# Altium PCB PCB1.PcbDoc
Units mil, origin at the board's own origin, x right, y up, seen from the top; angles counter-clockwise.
Board outline 6000 x 4000 mil, 2 copper layers (Top Layer, Bottom Layer); 44 components, 30 nets, 116 pads, 3 vias.
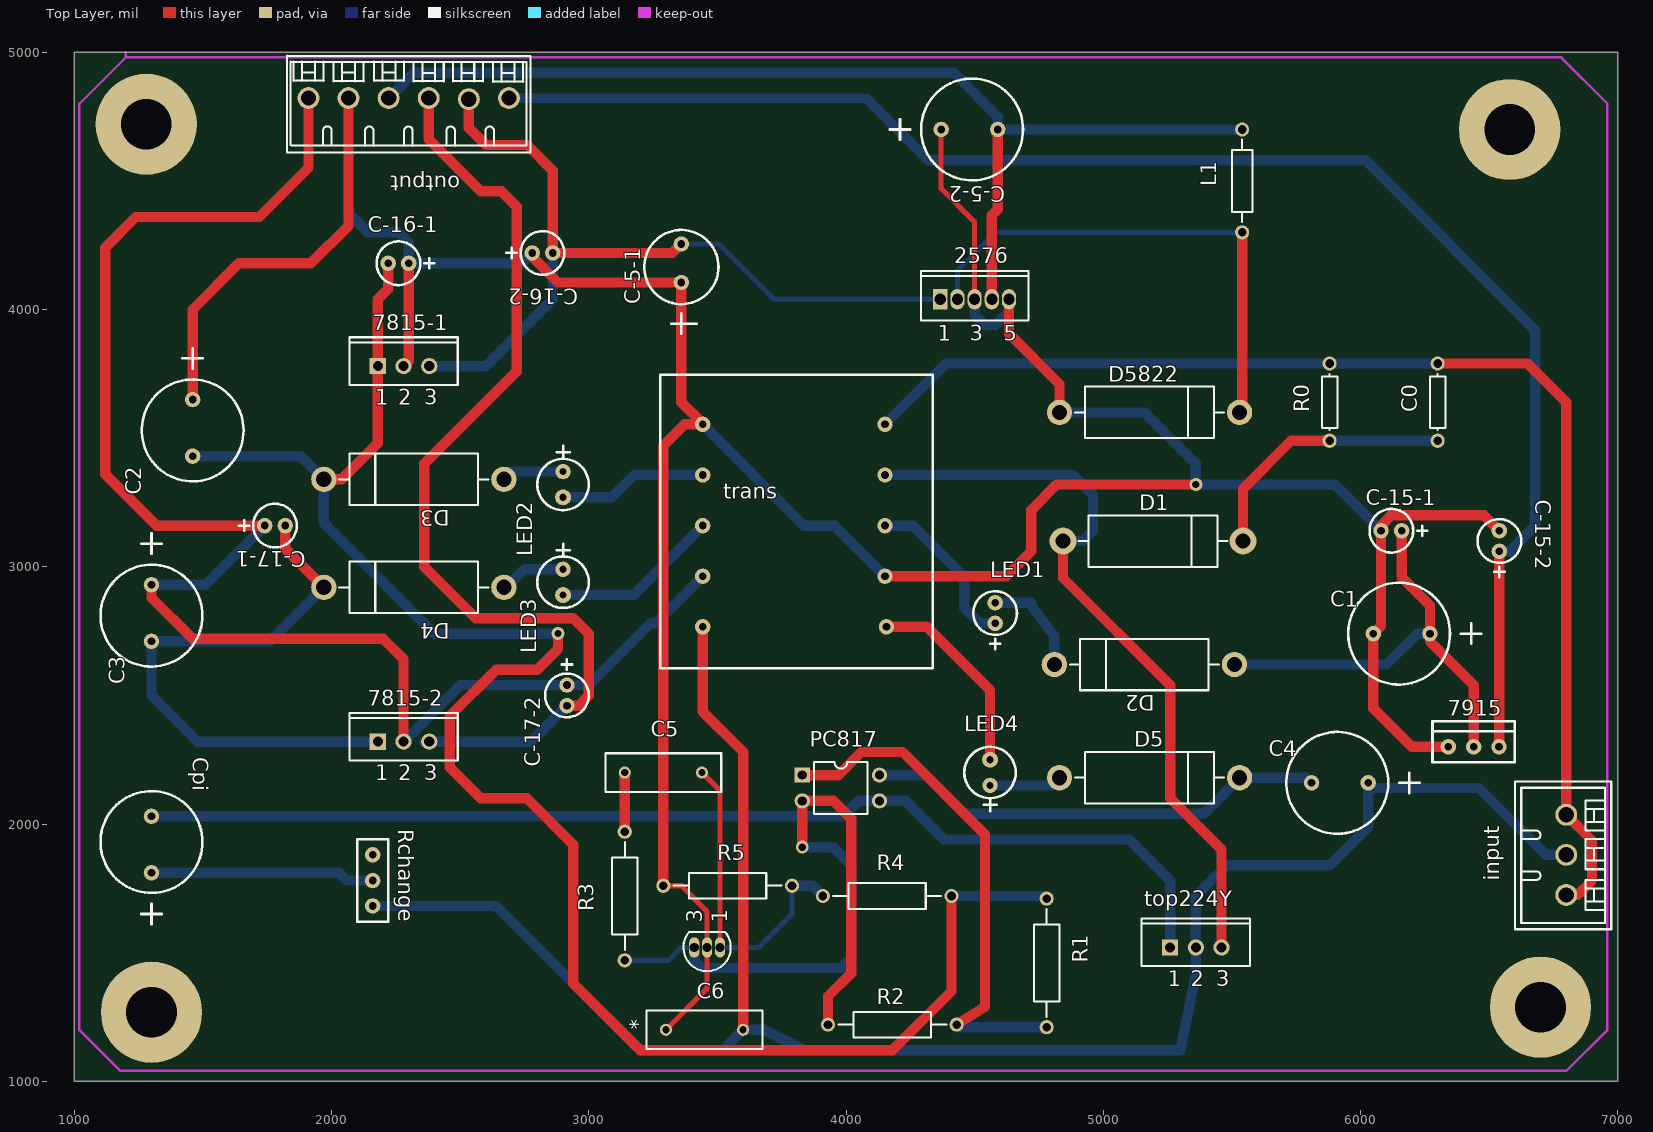
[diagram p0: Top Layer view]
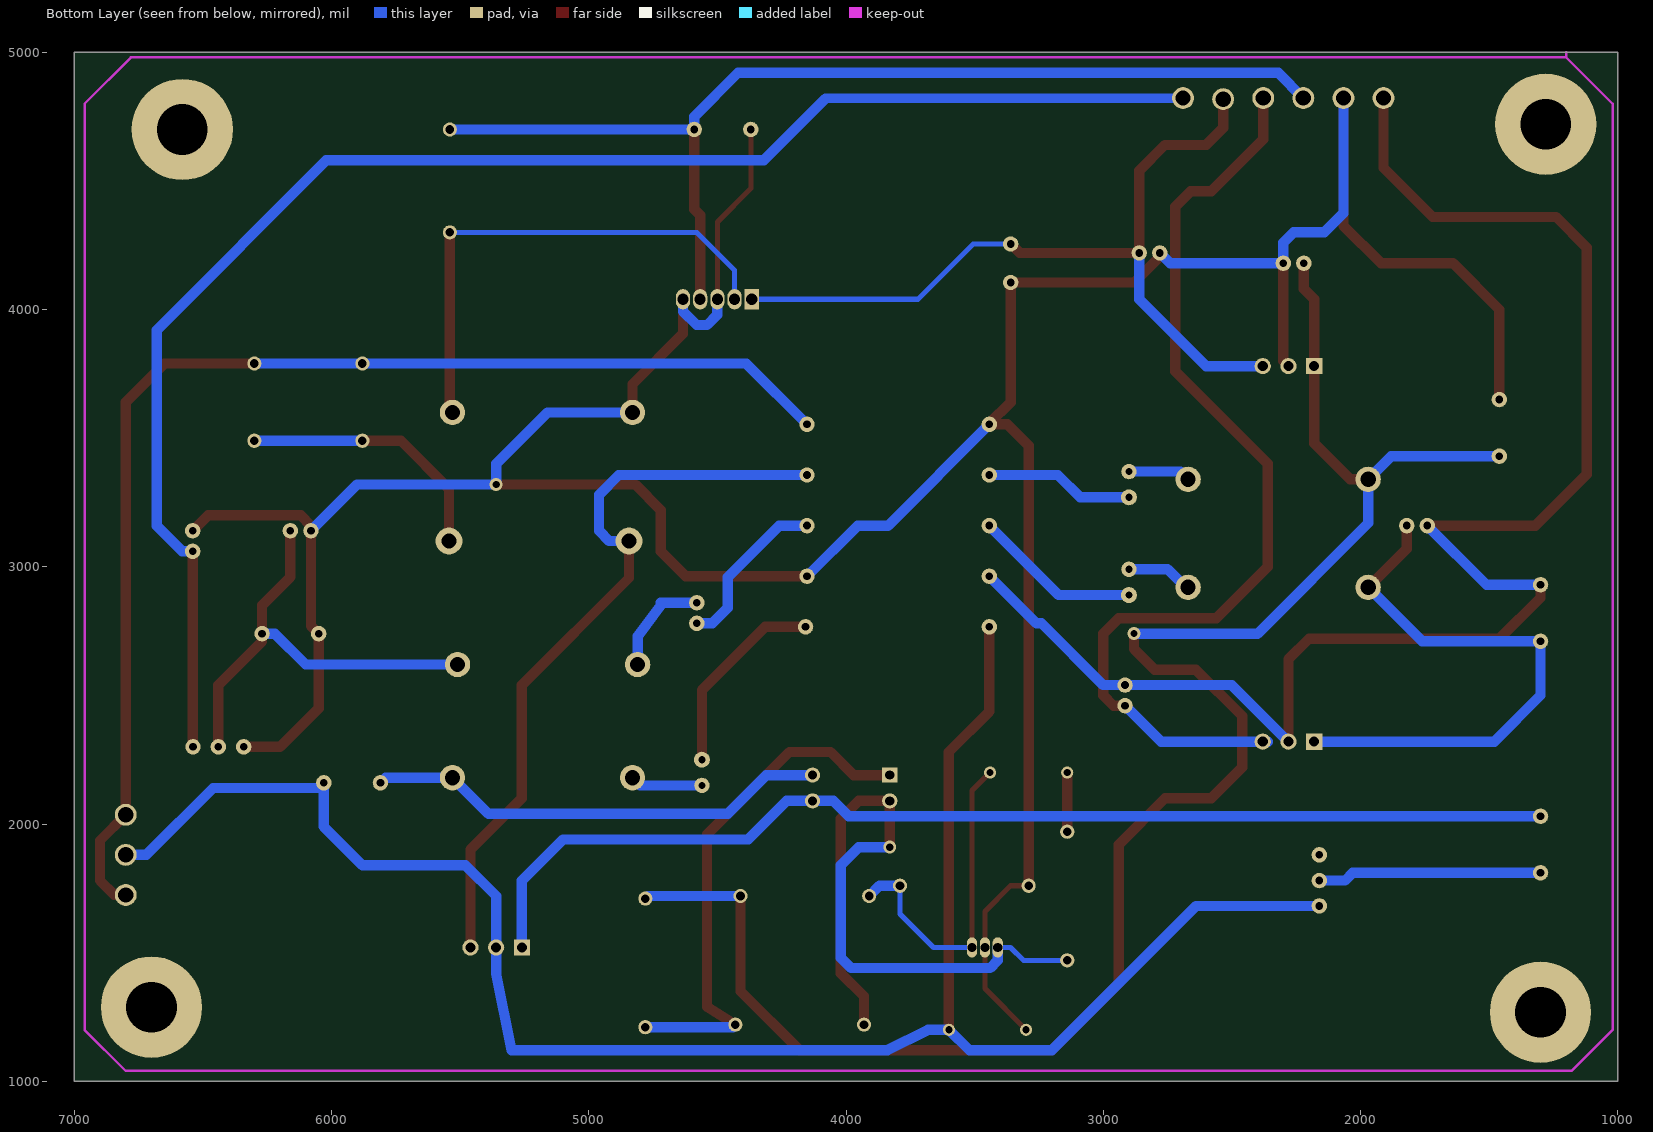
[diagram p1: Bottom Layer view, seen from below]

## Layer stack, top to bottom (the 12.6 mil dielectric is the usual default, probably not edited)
Top Layer: signal copper 1.4
Dielectric: dielectric 12.6, FR-4, Dk 4.8
Bottom Layer: signal copper 1.4

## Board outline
1000,1000 1000,5000 7000,5000 7000,1000

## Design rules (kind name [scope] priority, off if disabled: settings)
Clearance [All] p1: gap=10
ComponentClearance [All] p1: gap=10 collisioncheckmode=0
PolygonConnect [All] p1: connectstyle=Relief reliefconductorwidth=10 reliefentries=4 polygonreliefangle="90 Angle"
RoutingLayers [All] p1: top layer=Horizontal bottom layer=Vertical
RoutingVias [All] p1: holewidth=28 width=50 viastyle="Through Hole" minholewidth=28 minwidth=50 maxholewidth=28 maxwidth=50
SolderMaskExpansion [All] p1: expansion=4
TestPointUsage [All] p1: valid=0 allowmultiple=FALSE
Testpoint [All] p1: side=15 testpointundercomponent=TRUE minsize=40 maxsize=100 preferedsize=60 minholesize=0 maxholesize=40 preferedholesize=32 testpointgrid=1 style=1023 order=-539222988
Width [All] p1: maxlimit=40 minlimit=20 preferedwidth=40
10 further rules are at their usual default settings.

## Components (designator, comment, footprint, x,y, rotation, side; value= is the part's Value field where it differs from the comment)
2576 "TERMINAL5" SFM-T5/X1.4V 4500,4040 r0 top
7815-1 "TERMINAL3" SFM-T3/A4.7V 2280,3780 r0 top
7815-2 "TERMINAL3" SFM-T3/A4.7V 2280,2320 r0 top
7915 "TERMINAL3" L7915 6440,2300 r0 top
* "TL431" BCY-W3/D4.7 3460,1520 r90 top
C0 "Cap Pol1" AXIAL-0.3 6300,3640 r90 top
C1 "Cap Pol2" "5mmC - duplicate" 6160,2740 r0 top
C2 "Cap Pol2" "5mmC - duplicate" 1460,3540 r90 top
C3 "Cap Pol2" "5mmC - duplicate" 1300,2820 r90 top
C4 "Cap Pol2" "5mmC - duplicate" 5920,2160 r0 top
C5 "Cap" RAD-0.3 3440,2200 r180 top
C6 "Cap" RAD-0.3 3600,1200 r180 top
C-5-1 "Cap Pol2" 3.8mm 3360,4180 r90 top
C-5-2 "Cap Pol2" "5mmC - duplicate" 4480,4700 r180 top
C-15-1 "Cap Pol1" 2mmC#1 6120,3140 r0 top
C-15-2 "Cap Pol1" 2mmC#1 6540,3100 r270 top
C-16-1 "Cap Pol2" 2mmC#1 2260,4180 r0 top
C-16-2 "Cap Pol2" 2mmC#1 2820,4220 r180 top
C-17-1 "Cap Pol2" 2mmC#1 1780,3160 r180 top
C-17-2 "Cap Pol2" 2mmC#1 2915.15,2500 r90 top
Cpi "Cap Pol2" "5mmC - duplicate" 1300,1920 r270 top
D1 "D Zener" DIODE-0.7 5193.53,3100 r0 top
D2 "FR307" "DIODE 1.5" 5160,2620 r180 top
D3 "FR307" "DIODE 1.5" 2320,3340 r180 top
D4 "FR307" "DIODE 1.5" 2320,2920 r180 top
D5 "FR307" "DIODE 1.5" 5180,2180 r0 top
D5822 "D Zener" "DIODE 1.5" 5180,3600 r0 top (schematic designator D1)
input "MHDR1X3" COM3 6800,1880 r90 top
L1 "Inductor" AXIAL-0.4 5540,4500 r90 top
LED1 "LED1" 2mmC#2 4580,2820 r90 top
LED2 "LED1" LED 2900,3320 r90 top
LED3 "LED1" LED 2900,2940 r90 top
LED4 "LED1" LED 4560,2200 r270 top
output "Header 6H" COM6 2300,4820 r180 top
PC817 "GUANG OU" "guang ou" 3980,2140 r270 top
R0 "Res1" AXIAL-0.3 5880,3640 r90 top
R1 "Res Semi" AXIAL-0.5 4780,1460 r90 top
R2 "Res Semi" AXIAL-0.5 4180,1220 r180 top
R3 "Res Semi" AXIAL-0.5 3140,1720 r90 top
R4 "Res Semi" AXIAL-0.5 4160,1720 r0 top
R5 "Res Semi" AXIAL-0.5 3540,1760 r0 top
Rchange "Res Adj2" R2pin 2160,1780 r270 top
top224Y "PMOS-2" SFM-T3/A4.7V 5360,1520 r0 top
trans "TRANS" trans 3800,3160 r0 top

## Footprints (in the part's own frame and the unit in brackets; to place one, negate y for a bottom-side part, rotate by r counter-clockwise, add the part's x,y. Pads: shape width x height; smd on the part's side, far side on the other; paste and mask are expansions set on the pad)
2mmC#1 [mil]
  round 60 hole 30: 1(-40,0) 2(40,0)
  silkscreen extent -85,-85 140,85
2mmC#2 [mil]
  round 60 hole 30: 1(40,0) 2(-40,0)
  silkscreen extent -140,-85 85,85
3.8mm [mil]
  round 60 hole 30: 1(74.8,0) 2(-74.8,0)
  silkscreen extent -275,-144 129,144
"5mmC - duplicate" [mil]
  round 60 hole 30: 1(-110,0) 2(110,0)
  silkscreen extent -208,-198 310,198
AXIAL-0.3 [mm]
  round 1.4 hole 0.85: 1(-3.81,0) 2(3.81,0)
  silkscreen extent -2.77,-0.76 2.77,0.76
AXIAL-0.4 [mm]
  round 1.4 hole 0.85: 1(-5.08,0) 2(5.08,0)
  silkscreen extent -4.06,-1.02 4.06,1.02
AXIAL-0.5 [mm]
  round 1.4 hole 0.85: 1(-6.35,0) 2(6.35,0)
  silkscreen extent -5.33,-1.27 5.33,1.27
BCY-W3/D4.7 [mm]
  oval 2x1 hole 0.9: 1(0,-1.27) 2(0,0) 3(0,1.27)
  silkscreen extent -2.33,-2.33 1.55,2.33
COM3 [mil]
  round 85 hole 59.5: 1(-155.83,0) 2(0,0) 3(155.83,0)
  silkscreen extent -289,-175 286,200
COM6 [mil]
  round 85 hole 59.5: 1(-389.58,-2) 2(-233.75,2) 3(-77.92,-2) 4(77.92,-2) 5(233.75,-2) 6(389.58,-2)
  silkscreen extent -473,-167 474,210
"DIODE 1.5" [mm]
  round 2.5 hole 1.5: 1(-8.89,0) 2(8.89,0)
  silkscreen extent -7.37,-2.54 7.37,2.54
DIODE-0.7 [mm]
  round 2.65 hole 1.5: 1(-8.89,0) 2(8.89,0)
  silkscreen extent -7.37,-2.54 7.37,2.54
"guang ou" [mm]
  rect 1.5x1.5 hole 0.9: 1(-1.27,-3.81)
  round 1.5 hole 0.9: 2(1.27,-3.81) 3(1.27,3.81) 4(-1.27,3.81)
  silkscreen extent -2.55,-2.65 2.55,2.65
L7915 [mil]
  round 60 hole 30: 1(0,0) 2(-98.43,0) 3(98.43,0)
  silkscreen extent -160,-60 160,100
LED [mil]
  round 62 hole 28: 1(-50,0)
  round 60 hole 28: 2(50,0)
  silkscreen extent -100,-100 150,100
R2pin [mil]
  round 60 hole 30: 1(98.43,0) 2(0,0) ""(-100,0)
  silkscreen extent -160,-60 160,60
RAD-0.3 [mm]
  round 1.2 hole 0.7: 1(0,0) 2(7.62,0)
  silkscreen extent -1.91,-1.91 9.53,1.91
SFM-T3/A4.7V [mm]
  rect 1.6x1.6 hole 1: 1(-2.54,0)
  round 1.6 hole 1: 2(0,0) 3(2.54,0)
  silkscreen extent -5.35,-1.85 5.35,2.85
SFM-T5/X1.4V [mm]
  rect 1.4x2 hole 1.1: 1(-3.4,0)
  oval 1.4x2 hole 1.1: 2(-1.7,0) 3(0,0) 4(1.7,0) 5(3.4,0)
  silkscreen extent -5.3,-2.1 5.3,2.8
trans [mil]
  round 60 hole 30: 1(351.5,393.7) 2(351.5,196.85) 3(351.5,-196.85) 4(351.5,0) 5(-357.17,196.85) 6(-357.17,393.7) 7(-357.17,0) 8(-357.17,-196.85) 9(357.17,-393.7) 10(-357.17,-393.7)
  silkscreen extent -523,-554 537,586

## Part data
C0 C-15-1 C-15-2: "Polarized Capacitor (Radial)"
C1 C2 C3 C4 C-5-1 C-5-2 C-16-1 C-16-2 C-17-1 C-17-2 Cpi: "Polarized Capacitor (Axial)"
C5 C6: "Capacitor"
D1 D5822: "Zener Diode"
D2 D3 D4 D5: library part Diode, "Default Diode"
input: "Header, 3-Pin"
LED1 LED2 LED3 LED4: "Typical RED GaAs LED"
output: "Header, 6-Pin,  Right Angle"
R0: "Resistor"
R1 R2 R3 R4 R5: "Semiconductor Resistor"
Rchange: "Variable Resistor"
top224Y: "P-Channel Power MOSFET"

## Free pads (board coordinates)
  round 393.7 hole 196.85: 1(1280,4720) 2(6580,4700) 3(6700,1288) 4(1300,1268)

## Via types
v1: diameter 50, hole 28, Top Layer to Bottom Layer, 3 vias

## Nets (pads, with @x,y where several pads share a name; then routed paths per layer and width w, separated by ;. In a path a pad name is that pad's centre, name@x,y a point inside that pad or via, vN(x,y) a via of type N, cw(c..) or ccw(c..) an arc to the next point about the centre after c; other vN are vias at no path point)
5V: 2576.4 C-5-2.1 L1.2 output.4 | length 4148.5
  Top Layer w40: 2576.4 4566.93,4366.93 4590,4390 C-5-2.1
  Bottom Layer w40: output.4 2320.08,4920 4420,4920 4590,4750 C-5-2.1 L1.2
15V: 2576.1 7815-1.3 C-5-1.1 C-16-2.1 output.2 | length 3204.1
  Top Layer w40: output.2 2533.75,4706.25 2600,4640 2760,4640 2860,4540 C-16-2.1 3325.2,4220 C-5-1.1
  Bottom Layer w20: C-5-1.1 3505.2,4254.8 3720,4040 2576.1
  Bottom Layer w40: 7815-1.3 2600,3780 2860,4040 C-16-2.1
15VISO: 7815-2.3 C-17-2.1 output.3 | length 3861.9
  Top Layer w40: output.3 2377.92,4662.08 2580,4460 2660,4460 2720,4400 2720,3760 2360,3400 2360,3000 2560,2800 2940,2800 3000,2740 3000,2500 2960,2460 C-17-2.1
  Bottom Layer w40: 7815-2.3@2360,2320 2775.15,2320 C-17-2.1
-15V: 7915.3 C-15-2.2 output.1 | length 6065.3
  Top Layer w40: 7915.3 6540,2301.57 C-15-2.2
  Bottom Layer w40: output.1 4080,4820.16 ; 4080,4820 4320,4580 6020,4580 6680,3920 6680,3160 6580,3060 C-15-2.2
FEEDBACK: 7815-1.1 C2.1 C-16-1.1 D3.2 R1.2 R4.2 | length 7139
  Top Layer w40: D3.2 2040,3340 2180,3480 2180,4040 2220,4080 C-16-1.1 ; v1(2880,2740) 2880,2680 2800,2600 2640,2600 2460,2420 2460,2220 2580,2100 2760,2100 2940,1920 2940,1380 3200,1120 4180,1120 4410,1350 R4.2
  Bottom Layer w40: C2.1 1880,3430 D3.2 1970,3170 2400,2740 v1(2880,2740) ; R4.2 4770,1720 R1.2
GND1: 2576.3 2576.5 7815-1.2 7915.2 *.2 C1.1 C2.2 C6.2 C-5-1.2 C-5-2.2 C-15-1.1 C-15-2.1 C-16-1.2 C-16-2.2 D5822.1 output.5 R5.1 trans.3 trans.6 | length 14160.6
  Top Layer w20: R5.1 3360,1760 3460,1660 *.2 3460,1360 C6.2 ; C-5-2.2 4370,4470 4500,4340 2576.3
  Top Layer w40: C2.2 1460,4000 1640,4180 1920,4180 2066.25,4326.25 output.5 ; 7815-1.2 2300,3800 C-16-1.2 ; C-16-2.2 2780,4205.2 2880,4105.2 C-5-1.2 3360,3640 3442.83,3557.17 trans.6 3373.7,3553.7 3290,3470 R5.1 ; trans.3 4623.15,2963.15 4720,3060 4720,3220 4820,3320 v1(5360,3320) ; 2576.5 4633.86,3906.14 4830,3710 D5822.1@4830,3580 ; 7915.2 6200,2300 6050,2450 C1.1 6080,2770 6080,3160 6120,3200 6480,3200 C-15-2.1
  Bottom Layer w40: output.5 2066.25,4373.75 2140,4300 2260,4300 2300,4260 C-16-1.2 2740,4180 C-16-2.2 ; trans.6 3836.53,3160 3954.65,3160 trans.3 ; 2576.3 4500,3980 4540,3940 4580,3940 4633.86,3993.86 2576.5 ; D5822.1 5160,3600 5360,3400 v1(5360,3320) 5900,3320 C-15-1.1
GND2: 7815-2.2 C3.2 C-17-1.2 C-17-2.2 output.6 trans.8 | length 6187.3
  Top Layer w40: C3.2 1300,2880 1460,2720 2200,2720 2280,2640 7815-2.2 ; C-17-1.2 1320,3160 1120,3360 1120,4240 1240,4360 1720,4360 1910.42,4550.42 output.6
  Bottom Layer w40: C3.2 1510,2930 C-17-1.2 ; 7815-2.2 2500,2540 3000,2540 3240,2780 3259.68,2780 trans.8
GNDMAIN: C4.2 C6.1 input.2 Rchange.1 top224Y.2 trans.10 | length 7471.5
  Top Layer w40: trans.10 3442.83,2437.17 3600,2280 C6.1
  Bottom Layer w40: Rchange.1 2638.43,1681.57 3200,1120 3520,1120 C6.1 3680,1200 3840,1120 5300,1120 5360,1420 5360,1720 5480,1840 5880,1840 6030,1990 6030,2140 6460,2140 6720,1880 input.2
Net2576_2: 2576.2 D5822.2 L1.1 | length 2005
  Top Layer w40: D5822.2@5530,3580 5540,3590 L1.1
  Bottom Layer w20: 2576.2 4433.07,4153.07 4580,4300 L1.1
Net7815-2_1: 7815-2.1 C3.1 C-17-1.1 D4.2 | length 2223.7
  Top Layer w40: C-17-1.1 1820,3070 D4.2
  Bottom Layer w40: D4.2 1760,2710 C3.1 1300,2500 1480,2320 7815-2.1
Net7915_1: 7915.1 C1.2 C-15-1.2 D2.1 | length 1765.7
  Top Layer w40: C-15-1.2 6160,2960 6270,2850 6270,2710 6440,2540 7915.1
  Bottom Layer w40: D2.1 6100,2620 6220,2740 C1.2
Net*_1: *.1 C5.1 R4.1 R5.2 | length 1289.4
  Top Layer w20: C5.1 3510,2130 *.1
  Bottom Layer w20: *.1 3660,1520 3790,1650 R5.2
  Bottom Layer w40: R5.2 3870,1760 R4.1
Net*_3: *.3 PC817.2 R2.2 R3.1 | length 2795
  Top Layer w40: v1(3830,1910) PC817.2 3950,2090 4020,2020 4020,1420 3930,1330 R2.2
  Bottom Layer w20: R3.1 3310,1470 3360,1520 *.3
  Bottom Layer w40: *.3 3410,1470 3440,1440 3980,1440 4020,1480 4020,1840 3950,1910 v1(3830,1910)
NetC0_1: C0.1 D1.2 R0.1 | length 1037.2
  Top Layer w40: D1.2 5543.53,3303.53 5730,3490 R0.1
  Bottom Layer w40: R0.1 C0.1
NetC0_2: C0.2 input.1 input.3 R0.2 trans.1 | length 4833.1
  Top Layer w40: C0.2 6650,3790 6800,3640 input.3 6900,1935.83 6900,1780 6844.17,1724.17 input.1
  Bottom Layer w40: trans.1 4387.8,3790 C0.2
NetC4_1: C4.1 D5.2 PC817.4 | length 1808.4
  Bottom Layer w40: PC817.4 4310,2190 4460,2040 5390,2040 D5.2 5790,2180 C4.1
NetC5_2: C5.2 R3.2 | length 230
  Top Layer w40: R3.2 C5.2
NetCpi_1: Cpi.1 PC817.3 top224Y.1 | length 4373.3
  Bottom Layer w40: Cpi.1 3990,2030 4050,2090 4230,2090 4380,1940 5100,1940 5260,1780 top224Y.1
NetCpi_2: Cpi.2 Rchange.2 | length 872.4
  Bottom Layer w40: Cpi.2 2030,1810 2060,1780 Rchange.2
NetD1_1: D1.1 top224Y.3 trans.2 | length 2948.7
  Top Layer w40: D1.1 4843.53,2956.47 5260,2540 5260,2100 5460,1900 top224Y.3
  Bottom Layer w40: trans.2 4883.15,3356.85 4960,3280 4960,3140 4920,3100 D1.1
NetD2_2: D2.2 LED1.1 | length 412.5
  Bottom Layer w40: LED1.1 4720,2860 ; 4712.5,2860 4715.2,2856.4 4810,2730 D2.2
NetD3_1: D3.1 LED2.2 | length 242.4
  Bottom Layer w40: D3.1 2700,3370 LED2.2
NetD4_1: D4.1 LED3.2 | length 259
  Bottom Layer w40: D4.1 2680,2920 2750,2990 LED3.2
NetD5_1: D5.1 LED4.2 | length 282.4
  Bottom Layer w40: LED4.2 4800,2150 D5.1
NetLED1_1: 
NetLED1_2: LED1.2 trans.4 | length 656.2
  Bottom Layer w40: trans.4 4260,3160 4460,2960 4460,2840 4520,2780 LED1.2
NetLED2_1: LED2.1 trans.5 | length 578.8
  Bottom Layer w40: LED2.1 3090,3270 3176.85,3356.85 trans.5
NetLED3_1: LED3.1 trans.7 | length 654.7
  Bottom Layer w40: LED3.1 3172.83,2890 trans.7
NetLED4_1: LED4.1 trans.9 | length 774.9
  Top Layer w40: trans.9 4313.7,2766.3 4560,2520 LED4.1
NetPC817_1: PC817.1 R1.1 R2.1 | length 2034.4
  Top Layer w40: PC817.1 3970,2190 4060,2280 4220,2280 4540,1960 4540,1290 R2.1
  Bottom Layer w40: R2.1 4440,1210 R1.1
pads on no net: Rchange.

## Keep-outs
Keep-Out Layer:
  lines w10: 1200,5000 1200,4980 ; 1200,4980 6780,4980 6960,4800 6960,1200 6800,1040 1180,1040 1020,1200 1020,4800 1200,4980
